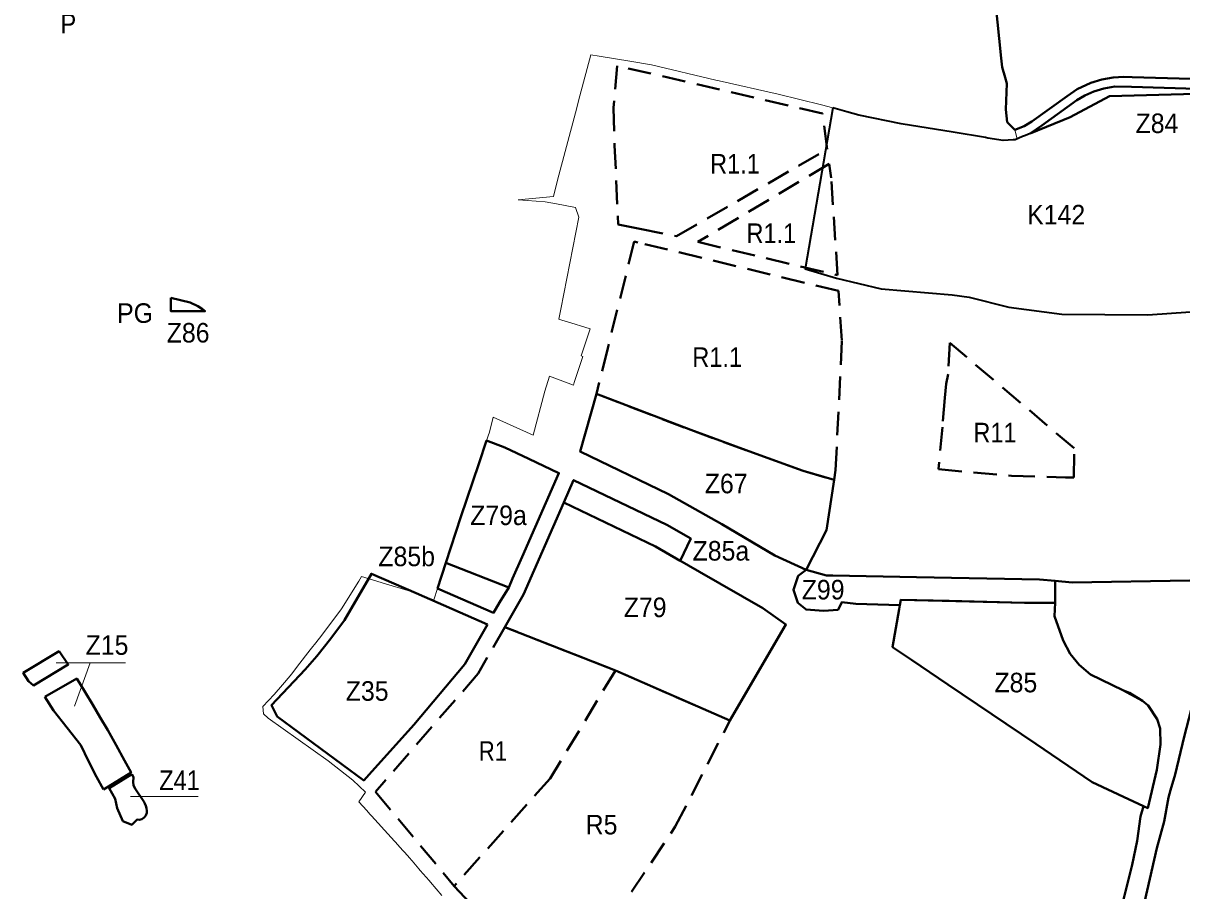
# Model space of a CAD drawing. Extents: x -650276 to -642489, y -1074425 to -1066658.
# Drawn here: x -646636 to -645214, y -1071749 to -1070685 of the extents above; entities that cross this region are included whole.
import ezdxf

# ---------------------------------------------------------------- set-up
doc = ezdxf.new("R2010")
doc.units = 0
doc.header["$LTSCALE"] = 9.6
doc.linetypes.add('MEDIUM_DASHED', pattern=[4.5, 3, -1.5])
for name, color, linetype, lineweight in [('1', 7, 'Continuous', 13), ('43', 7, 'Continuous', 13), ('44', 7, 'Continuous', 40), ('45', 7, 'Continuous', 40), ('46', 7, 'Continuous', 13), ('5', 7, 'Continuous', 35), ('60', 7, 'Continuous', 35), ('61', 7, 'MEDIUM_DASHED', 40), ('62', 7, 'Continuous', 35)]:
    doc.layers.add(name, color=color, linetype=linetype, lineweight=lineweight)

msp = doc.modelspace()

# ---------------------------------------------------------------- linework, layer by layer
at = {"layer": '1'}
for points in [[(-645428.73, -1070758.67), (-645434.53, -1070738.77), (-645449.82, -1070592.72), (-645448.36, -1070563), (-645454.02, -1070501.52), (-645458.46, -1070478.86), (-645458.32, -1070455.91), (-645470.99, -1070428.07)], [(-646122.16, -1071754.78), (-646136.17, -1071738.31), (-646137.84, -1071736.34), (-646148.49, -1071723.82), (-646150.15, -1071721.86), (-646158.35, -1071712.22), (-646162.04, -1071708.13), (-646163.9, -1071706.08), (-646174.08, -1071694.82), (-646175.81, -1071692.91), (-646184.36, -1071683.46), (-646208.56, -1071656.73), (-646210.29, -1071654.83), (-646214.19, -1071650.52), (-646224.128, -1071639.584), (-646215.81, -1071627.86), (-646231.43, -1071613.06), (-646261.46, -1071589.38), (-646335.3, -1071537.05), (-646340.93, -1071531.64), (-646341.88, -1071522.81), (-646327.97, -1071508.29), (-646317.52, -1071496.12), (-646315.22, -1071493.44), (-646306.14, -1071482.86), (-646299.18, -1071473.54), (-646283.52, -1071453.34), (-646281.99, -1071451.4), (-646276.82, -1071444.86), (-646269.2, -1071435.22), (-646245.1, -1071403.04), (-646223.77, -1071369.24), (-646220.61, -1071363.16), (-646191.35, -1071372.15), (-646163.84, -1071380.66), (-646131.79, -1071391.83), (-646127.301, -1071378.036), (-646098.66, -1071290.03), (-646067.097, -1071196.699), (-646063.59, -1071186.33), (-646059.28, -1071167.97), (-646010.14, -1071190.08), (-645995.74, -1071136.22), (-645990.14, -1071117.76), (-645960.66, -1071128.71), (-645959.58, -1071125.39), (-645949.21, -1071093.62), (-645950.96, -1071092.8), (-645941.45, -1071063.3), (-645940.25, -1071059.59), (-645968.97, -1071050.66), (-645973.77, -1071049.17), (-645978.58, -1071047.68), (-645976.17, -1071035.39), (-645954.01, -1070922.8), (-645958.21, -1070910.84), (-645981.48, -1070906.35), (-645995.33, -1070903.68), (-646028.42, -1070901.38), (-645985.28, -1070897.13), (-645980.01, -1070877.28), (-645958.12, -1070794.72), (-645952.65, -1070773.98), (-645939.27, -1070723.43), (-645929.077, -1070725.07), (-645891.35, -1070731.13), (-645865, -1070735.66), (-645785.75, -1070754.48), (-645781.62, -1070755.42), (-645709.54, -1070771.74), (-645656.2, -1070784.96), (-645642.52, -1070788.7), (-645625, -1070793.5), (-645610.25, -1070797.55), (-645577.54, -1070804.13), (-645558.3, -1070808), (-645494.82, -1070818.45), (-645452.31, -1070825.52), (-645433.49, -1070828.76), (-645421.09, -1070827.89), (-645418.67, -1070827.72), (-645416.08, -1070826.618), (-645419.18, -1070815.44), (-645424.969, -1070809.563), (-645428.39, -1070806.09), (-645430, -1070790.68), (-645428.73, -1070758.67)]]:
    msp.add_lwpolyline(points, dxfattribs=at)
at = {"layer": '44'}
msp.add_line((-645369.665, -1071395.694), (-645370.24, -1071411.83), dxfattribs=at)
for points in [[(-645275.8, -1070762.66), (-645195.527, -1070765.319), (-645156.988, -1070766.884), (-645100.32, -1070769.5), (-645081.6, -1070770.362), (-645081.75, -1070772.79), (-645125.217, -1070770.81), (-645143, -1070770), (-645161, -1070770), (-645182, -1070771), (-645303, -1070774), (-645351, -1070800), (-645400.05, -1070819.84), (-645385.99, -1070810.35), (-645342.94, -1070779.31), (-645333.12, -1070773.33), (-645321.9, -1070768.47), (-645309.78, -1070764.88), (-645296.51, -1070762.52)], [(-646454.59, -1071021.54), (-646454.59, -1071038), (-646412.54, -1071038.01), (-646415.61, -1071035.4), (-646421.58, -1071031.81), (-646430.91, -1071027.44)], [(-645829.706, -1071343.963), (-645816.714, -1071316.828), (-645846, -1071300), (-645960.34, -1071245.09), (-645972.422, -1071272.568), (-645859.986, -1071326.563)], [(-646117.031, -1071346.48), (-646127.301, -1071378.036), (-646058.719, -1071407.796), (-646051.148, -1071395.208), (-646040.084, -1071376.813)]]:
    msp.add_lwpolyline(points, close=True, dxfattribs=at)
for points in [[(-645407.045, -1071395.646), (-645499.65, -1071393.3), (-645558.872, -1071391.801), (-645560.11, -1071398.7), (-645614.201, -1071396.844), (-645631.44, -1071394.9), (-645635.795, -1071404.403), (-645653.742, -1071405.36), (-645675.177, -1071403.922), (-645685.098, -1071395.824), (-645690.677, -1071379.721), (-645684.785, -1071362.539), (-645674.947, -1071355.071), (-645650.28, -1071362.07), (-645642.431, -1071362.259), (-645539.738, -1071364.092)], [(-645539.738, -1071364.092), (-645388.619, -1071366.991), (-645369.696, -1071368.676)], [(-645369.67, -1071368.678), (-645369.665, -1071395.694), (-645407.045, -1071395.646)], [(-645204.341, -1071368.19), (-645348.55, -1071370.559), (-645369.67, -1071368.678)], [(-645370.24, -1071411.83), (-645369.665, -1071395.694), (-645407.045, -1071395.646), (-645558.872, -1071391.801), (-645560.11, -1071398.7), (-645560.94, -1071403.441)], [(-645222.48, -1071606.08), (-645211.27, -1071560.01), (-645199.61, -1071515.68), (-645186.67, -1071465.55), (-645175.06, -1071420.93), (-645167.58, -1071421.19), (-645167.37, -1071415.2), (-645163.56, -1071415.3), (-645164.76, -1071401.79), (-645166.34, -1071384.07)], [(-645560.94, -1071403.441), (-645569.07, -1071449.88), (-645545.817, -1071465.611)], [(-645370.24, -1071411.83), (-645359.64, -1071442), (-645351.06, -1071458.3), (-645340.16, -1071471.63), (-645326.29, -1071483.41), (-645286.62, -1071502.67), (-645278.52, -1071506.12)], [(-645326.29, -1071483.41), (-645340.16, -1071471.63), (-645351.06, -1071458.3), (-645359.64, -1071442), (-645370.24, -1071411.83)], [(-645545.817, -1071465.611), (-645501.37, -1071495.68), (-645393.34, -1071568.75)], [(-645279.531, -1071636.404), (-645261.094, -1071645.025), (-645256.02, -1071647.398), (-645244.81, -1071600.61), (-645240.26, -1071569.52), (-645240.82, -1071549.6), (-645244.4, -1071538.48), (-645255.51, -1071521.55), (-645262.36, -1071515.72), (-645286.62, -1071502.67), (-645326.29, -1071483.41)], [(-645278.52, -1071506.12), (-645262.36, -1071515.72), (-645255.51, -1071521.55), (-645244.4, -1071538.48), (-645240.82, -1071549.6), (-645240.26, -1071569.52), (-645244.81, -1071600.61), (-645256.02, -1071647.398), (-645261.094, -1071645.025)], [(-645393.34, -1071568.75), (-645324.17, -1071615.53), (-645279.531, -1071636.404)], [(-645347.551, -1072443.527), (-645347.677, -1072391.355), (-645346.62, -1072330.914), (-645343.458, -1072278.998), (-645339.908, -1072235.158), (-645335.367, -1072185.207), (-645325.498, -1072102.789), (-645309.01, -1071998.147), (-645285.617, -1071875.733), (-645244.798, -1071696.585), (-645235.793, -1071663.703), (-645230.436, -1071634.261), (-645227.905, -1071625.277), (-645222.48, -1071606.08)], [(-645261.094, -1071645.025), (-645264.841, -1071657.687), (-645269.077, -1071687.396), (-645274.868, -1071717.176), (-645286.175, -1071761.228), (-645300.076, -1071820.179), (-645313.153, -1071883.081)]]:
    msp.add_lwpolyline(points, dxfattribs=at)
at = {"layer": '45'}
msp.add_line((-646609.21, -1071510.98), (-646570, -1071488.38), dxfattribs=at)
msp.add_line((-646609.21, -1071510.98), (-646570, -1071488.38), dxfattribs=at)
for points in [[(-645674.947, -1071355.071), (-645650.09, -1071306.433), (-645640.737, -1071244.963), (-645678.86, -1071233.58), (-645741.09, -1071211.36), (-645816.47, -1071183.63), (-645932.502, -1071139.426), (-645952.419, -1071210.117), (-645844.079, -1071262.487), (-645778.69, -1071299.362), (-645713.428, -1071337.765)], [(-646067.097, -1071196.699), (-646044.944, -1071205.157), (-646015.387, -1071218.854), (-645978.403, -1071236.481), (-646023.652, -1071339.428), (-646035.241, -1071365.795), (-646040.084, -1071376.813), (-646117.031, -1071346.48), (-646098.66, -1071290.03), (-646076.713, -1071225.138)], [(-645768.62, -1071540.17), (-645699.825, -1071422.134), (-645728.054, -1071402.382), (-645806.036, -1071357.564), (-645859.986, -1071326.563), (-645972.422, -1071272.568), (-646022.073, -1071385.273), (-646044.948, -1071425.333), (-645909.13, -1071478.56)], [(-645768.62, -1071540.17), (-645699.825, -1071422.134), (-645728.054, -1071402.382), (-645806.036, -1071357.564), (-645859.986, -1071326.563), (-645972.422, -1071272.568), (-646022.073, -1071385.273), (-646044.948, -1071425.333), (-645909.13, -1071478.56)], [(-646066.165, -1071422.155), (-646153.5, -1071383.85), (-646208.577, -1071360.044), (-646241.68, -1071416.887), (-646258.487, -1071439.265), (-646275.615, -1071460.886), (-646289.976, -1071477.514), (-646330.914, -1071521.11), (-646324, -1071535), (-646217.978, -1071613.552), (-646211.407, -1071606.247), (-646156.471, -1071545.166), (-646094.063, -1071471.007)], [(-646066.165, -1071422.155), (-646153.5, -1071383.85), (-646208.577, -1071360.044), (-646241.68, -1071416.887), (-646258.487, -1071439.265), (-646275.615, -1071460.886), (-646289.976, -1071477.514), (-646330.914, -1071521.11), (-646324, -1071535), (-646217.978, -1071613.552), (-646211.407, -1071606.247), (-646156.471, -1071545.166), (-646094.063, -1071471.007)], [(-646591.65, -1071454.91), (-646635.79, -1071481.6), (-646629.37, -1071491.74), (-646623.18, -1071496.99), (-646580.58, -1071471.48)], [(-646591.65, -1071454.91), (-646635.79, -1071481.6), (-646629.37, -1071491.74), (-646623.18, -1071496.99), (-646580.58, -1071471.48)], [(-646502.39, -1071605.72), (-646530.27, -1071622.79), (-646522.99, -1071636.22), (-646520.32, -1071647.59), (-646513.43, -1071663.64), (-646502.53, -1071667.82), (-646496.06, -1071661.5), (-646492.89, -1071661.75), (-646490.07, -1071660.88), (-646487.36, -1071659.1), (-646485.29, -1071656.53), (-646484.15, -1071653.38), (-646483.97, -1071650.63), (-646484.38, -1071647.41), (-646485.2, -1071644.85), (-646486.31, -1071641.97), (-646487.56, -1071639.23), (-646497.83, -1071624.02), (-646499.829, -1071620.704), (-646500.289, -1071619.291), (-646500.83, -1071615.62), (-646500.34, -1071609.66)], [(-646502.39, -1071605.72), (-646530.27, -1071622.79), (-646522.99, -1071636.22), (-646520.32, -1071647.59), (-646513.43, -1071663.64), (-646502.53, -1071667.82), (-646496.06, -1071661.5), (-646492.89, -1071661.75), (-646490.07, -1071660.88), (-646487.36, -1071659.1), (-646485.29, -1071656.53), (-646484.15, -1071653.38), (-646483.97, -1071650.63), (-646484.38, -1071647.41), (-646485.2, -1071644.85), (-646486.31, -1071641.97), (-646487.56, -1071639.23), (-646497.83, -1071624.02), (-646499.829, -1071620.704), (-646500.289, -1071619.291), (-646500.83, -1071615.62), (-646500.34, -1071609.66)]]:
    msp.add_lwpolyline(points, close=True, dxfattribs=at)
for points in [[(-646570, -1071488.38), (-646559.53, -1071505.12), (-646550.23, -1071520.88), (-646541.14, -1071536.3), (-646532.04, -1071551.72), (-646521.8, -1071570.34), (-646511.47, -1071589.11), (-646503.31, -1071603.95), (-646531.2, -1071621.07), (-646537.28, -1071624.8)], [(-646570, -1071488.38), (-646559.53, -1071505.12), (-646550.23, -1071520.88), (-646541.14, -1071536.3), (-646532.04, -1071551.72), (-646521.8, -1071570.34), (-646511.47, -1071589.11), (-646503.31, -1071603.95), (-646531.2, -1071621.07), (-646537.28, -1071624.8)], [(-646537.28, -1071624.8), (-646545.89, -1071609.07), (-646555.78, -1071589.66), (-646565.17, -1071570.4), (-646598.63, -1071527.8), (-646609.21, -1071510.98)], [(-646537.28, -1071624.8), (-646545.89, -1071609.07), (-646555.78, -1071589.66), (-646565.17, -1071570.4), (-646598.63, -1071527.8), (-646609.21, -1071510.98)]]:
    msp.add_lwpolyline(points, dxfattribs=at)
at = {"layer": '46'}
for p, q in [((-646510.087, -1071469.269), (-646595.257, -1071469.269)), ((-646510.087, -1071469.269), (-646595.257, -1071469.269)), ((-646421.181, -1071633.007), (-646504.11, -1071633.007)), ((-646421.181, -1071633.007), (-646504.11, -1071633.007))]:
    msp.add_line(p, q, dxfattribs=at)
msp.add_lwpolyline([(-646510.087, -1071469.269), (-646553.419, -1071469.269), (-646572.844, -1071522.353)], dxfattribs=at)
msp.add_lwpolyline([(-646510.087, -1071469.269), (-646553.419, -1071469.269), (-646572.844, -1071522.353)], dxfattribs=at)
at = {"layer": '5', "lineweight": 40}
for points in [[(-645435.711, -1070727.497), (-645442.836, -1070659.455), (-645442.834, -1070659.455)], [(-645275.236, -1070750.954), (-645285.11, -1070750.69), (-645298.41, -1070751.48), (-645312.2, -1070753.77), (-645325.82, -1070757.94), (-645342.41, -1070765.76), (-645354.98, -1070774.28), (-645398.04, -1070805.44), (-645407.37, -1070810.95), (-645419.18, -1070815.44), (-645424.969, -1070809.563), (-645428.39, -1070806.09), (-645430, -1070790.68), (-645428.73, -1070758.67), (-645430.84, -1070751.43), (-645434.53, -1070738.77), (-645435.711, -1070727.497)], [(-645070.3, -1070755.92), (-645079.38, -1070756.91), (-645085.58, -1070758.04), (-645163.06, -1070754.64), (-645202.96, -1070752.89), (-645275.236, -1070750.954)]]:
    msp.add_lwpolyline(points, dxfattribs=at)
at = {"layer": '5'}
for points in [[(-645100.268, -1070771.946), (-645143, -1070770), (-645161, -1070770), (-645182, -1070771), (-645303, -1070774), (-645351, -1070800), (-645400.05, -1070819.84), (-645406.09, -1070822.34), (-645409.52, -1070823.76), (-645418.67, -1070827.72), (-645421.09, -1070827.89), (-645433.49, -1070828.76), (-645452.31, -1070825.52), (-645455.184, -1070825.042)], [(-645642.52, -1070788.7), (-645676.292, -1070985.89), (-645637.94, -1070997.4), (-645583.18, -1071010.7), (-645495.87, -1071017.81)], [(-645455.184, -1070825.042), (-645494.82, -1070818.45), (-645558.3, -1070808), (-645610.25, -1070797.55), (-645625, -1070793.5), (-645642.52, -1070788.7)], [(-645495.87, -1071017.81), (-645475.01, -1071020.72), (-645426.38, -1071032.8), (-645361.54, -1071041.54), (-645255.93, -1071042.36), (-645203.66, -1071038.81), (-645193.24, -1071037.31), (-645186.18, -1071030.83), (-645180.72, -1071028.86), (-645178.73, -1070972.35), (-645167.47, -1070975.2), (-645134.973, -1070977.077), (-645134.973, -1070977.077), (-645130.749, -1070959.561)]]:
    msp.add_lwpolyline(points, dxfattribs=at)
at = {"layer": '61'}
msp.add_line((-645909.13, -1071478.56), (-646044.948, -1071425.333), dxfattribs=at)
for points in [[(-645905.795, -1070931.641), (-645879, -1070937), (-645834, -1070946), (-645649.136, -1070839.223), (-645655.04, -1070795.257), (-645907.061, -1070736.979), (-645911.345, -1070788.463), (-645910.048, -1070834.649)], [(-645646.718, -1070857.232), (-645808, -1070953), (-645636.529, -1070993.874), (-645644.425, -1070874.306)], [(-645881.661, -1070953.494), (-645885.966, -1070952.452), (-645918.57, -1071083.449), (-645932.502, -1071139.426), (-645816.47, -1071183.63), (-645741.09, -1071211.36), (-645678.86, -1071233.58), (-645640.737, -1071244.963), (-645638.935, -1071233.122), (-645631.241, -1071073.956), (-645635.256, -1071013.15)], [(-645512.84, -1071231.9), (-645423.08, -1071239.85), (-645356.794, -1071241.776), (-645346.67, -1071242.07), (-645346.31, -1071206.07), (-645498.931, -1071076.631), (-645500.94, -1071115.24), (-645503.08, -1071126.98), (-645504.79, -1071144.18), (-645507.84, -1071180.326)], [(-645909.13, -1071478.56), (-645989, -1071611), (-646107, -1071743), (-645987.026, -1071872.902), (-645913.616, -1071786.041), (-645835.644, -1071670.191), (-645768.62, -1071540.17)]]:
    msp.add_lwpolyline(points, close=True, dxfattribs=at)
msp.add_lwpolyline([(-646044.948, -1071425.333), (-646077.593, -1071482.499), (-646203.387, -1071627.322), (-646107, -1071743)], dxfattribs=at)

# ---------------------------------------------------------------- texts
at = {"layer": '43', "width": 0.95}
msp.add_text('K142', height=24, dxfattribs=at).set_placement((-645403.889, -1070931.543))
at = {"layer": '44', "width": 0.95}
for s, p in [('Z84', (-645270.865, -1070819.478)), ('Z86', (-646459.658, -1071076.35)), ('Z86', (-646459.658, -1071076.35)), ('Z85b', (-646199.969, -1071350.698)), ('Z85a', (-645814.405, -1071343.847)), ('Z85a', (-645814.405, -1071343.847)), ('Z99', (-645680.485, -1071391.504)), ('Z99', (-645680.485, -1071391.504)), ('Z85', (-645444.048, -1071505.433)), ('Z85', (-645444.048, -1071505.433))]:
    msp.add_text(s, height=24, dxfattribs=at).set_placement(p)
at = {"layer": '46'}
for s, width, p in [('Z67', 0.95, (-645799.458, -1071261.304)), ('Z67', 0.95, (-645799.458, -1071261.304)), ('Z79a', 0.95, (-646087.322, -1071300.282)), ('Z79', 0.95, (-645898.897, -1071413.165)), ('Z79', 0.95, (-645898.897, -1071413.165)), ('Z15', 0.95, (-646559.155, -1071459.428)), ('Z15', 0.95, (-646559.155, -1071459.428)), ('Z35', 0.95, (-646239.99, -1071515.768)), ('Z35', 0.95, (-646239.99, -1071515.768)), ('Z41', 0.9, (-646468.869, -1071625.297)), ('Z41', 0.9, (-646468.869, -1071625.297))]:
    msp.add_text(s, height=24, dxfattribs=dict(at, width=width)).set_placement(p)
at = {"layer": '60'}
for s, width, p in [('P', 0.9, (-646590.032, -1070697.137)), ('PG', 0.95, (-646520.539, -1071052.252)), ('PG', 0.95, (-646520.539, -1071052.252))]:
    msp.add_text(s, height=24, dxfattribs=dict(at, width=width)).set_placement(p)
at = {"layer": '62'}
for s, width, p in [('R1.1', 0.9, (-645792.947, -1070869.095)), ('R1.1', 0.9, (-645748.253, -1070954.32)), ('R1.1', 0.9, (-645814.758, -1071106.298)), ('R11', 0.9, (-645469.881, -1071198.853)), ('R1', 0.85, (-646076.842, -1071589.396)), ('R5', 0.95, (-645945.557, -1071679.725)), ('R5', 0.95, (-645945.557, -1071679.725))]:
    msp.add_text(s, height=24, dxfattribs=dict(at, width=width)).set_placement(p)

doc.saveas('drawing.dxf')
